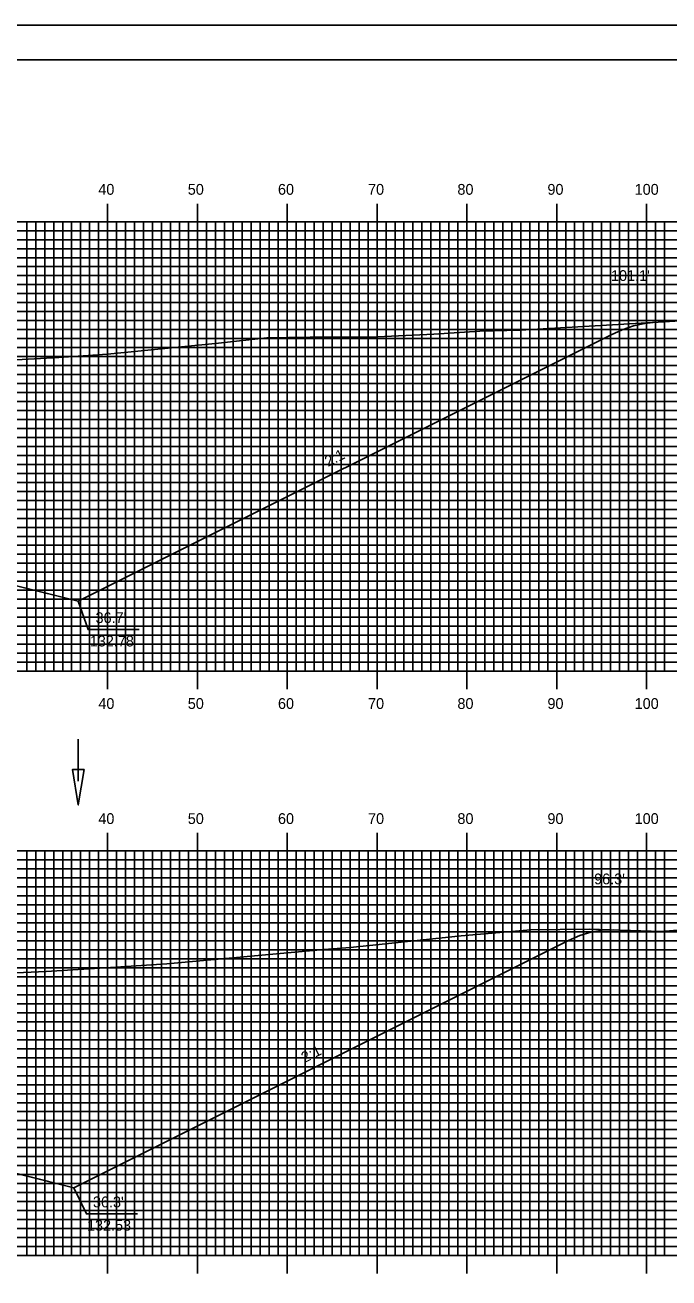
# Model space of a CAD drawing. Extents: x 1783041 to 1783384, y 442591 to 442811.
# Drawn here: x 1783237.3 to 1783309, y 442671.2 to 442810.5 of the extents above; entities that cross this region are included whole.
import ezdxf

# ---------------------------------------------------------------- set-up
doc = ezdxf.new("R2010")
doc.units = 0
for name, color, linetype in [('ANNOTATION', 7, 'Continuous'), ('BORDER', 7, 'Continuous'), ('D_Drainage_Ditch_Line', 7, 'Continuous'), ('D_Roadway_Centerline', 7, 'Continuous'), ('D_Roadway_SlopeLines', 7, 'Continuous'), ('D_Text_Standard', 7, 'Continuous'), ('H_V ANNOTATION', 7, 'Continuous'), ('MAJOR', 7, 'Continuous'), ('MINOR', 7, 'Continuous'), ('PLOT BOUNDARY', 7, 'Continuous'), ('S_Roadway_Centerline', 7, 'Continuous')]:
    doc.layers.add(name, color=color, linetype=linetype)

msp = doc.modelspace()

# ---------------------------------------------------------------- linework, layer by layer
at = {"layer": 'ANNOTATION'}
for points in [[(1783249.98, 442743.3), (1783244.29, 442743.3), (1783243.2, 442746.45)], [(1783249.8, 442678.3), (1783244.11, 442678.3), (1783242.72, 442681.2)]]:
    msp.add_lwpolyline(points, dxfattribs=at)
at = {"layer": 'BORDER'}
msp.add_lwpolyline([(1783056.86, 442596.67), (1783376.86, 442596.67), (1783376.86, 442806.67), (1783056.86, 442806.67)], close=True, dxfattribs=at)
at = {"layer": 'D_Drainage_Ditch_Line'}
msp.add_line((1783243.2, 442726.42), (1783243.2, 442731.12), dxfattribs=at)
msp.add_lwpolyline([(1783243.86, 442727.73), (1783242.54, 442727.73), (1783243.2, 442723.8)], close=True, dxfattribs=at)
at = {"layer": 'D_Roadway_Centerline'}
for points in [[(1783130.65, 442766.39), (1783131.9, 442766.43), (1783133.15, 442766.28), (1783134.4, 442765.93), (1783135.65, 442765.4), (1783172.29, 442747.09), (1783176.29, 442748.09), (1783186.46, 442750.63), (1783194.46, 442750.95), (1783206.46, 442751.19), (1783218.46, 442750.95), (1783226.46, 442750.63), (1783236.63, 442748.09), (1783243.2, 442746.45), (1783302.51, 442776.1), (1783303.76, 442776.66), (1783305.01, 442777.08), (1783306.26, 442777.35), (1783307.51, 442777.49)], [(1783136.28, 442698.26), (1783137.53, 442698.27), (1783138.78, 442698.11), (1783140.03, 442697.76), (1783141.28, 442697.22), (1783172.29, 442681.72), (1783176.29, 442682.72), (1783186.46, 442685.26), (1783194.46, 442685.58), (1783206.46, 442685.82), (1783218.46, 442685.58), (1783226.46, 442685.26), (1783236.63, 442682.72), (1783242.72, 442681.2), (1783297.77, 442708.72), (1783299.02, 442709.26), (1783300.27, 442709.64), (1783301.52, 442709.85), (1783302.77, 442709.89)]]:
    msp.add_lwpolyline(points, dxfattribs=at)
at = {"layer": 'D_Roadway_SlopeLines'}
for points in [[(1783243.2, 442746.45), (1783302.51, 442776.1), (1783303.76, 442776.66), (1783305.01, 442777.08), (1783306.26, 442777.35), (1783307.51, 442777.49)], [(1783226.46, 442750.63), (1783243.2, 442746.45)], [(1783242.72, 442681.2), (1783297.77, 442708.72), (1783299.02, 442709.26), (1783300.27, 442709.64), (1783301.52, 442709.85), (1783302.77, 442709.89)], [(1783226.46, 442685.26), (1783242.72, 442681.2)]]:
    msp.add_lwpolyline(points, dxfattribs=at)
at = {"layer": 'MAJOR'}
for p, q in [((1783246.46, 442790.67), (1783246.46, 442788.67)), ((1783256.46, 442790.67), (1783256.46, 442788.67)), ((1783266.46, 442790.67), (1783266.46, 442788.67)), ((1783276.46, 442790.67), (1783276.46, 442788.67)), ((1783286.46, 442790.67), (1783286.46, 442788.67)), ((1783296.46, 442790.67), (1783296.46, 442788.67)), ((1783306.46, 442790.67), (1783306.46, 442788.67)), ((1783066.46, 442788.67), (1783346.46, 442788.67)), ((1783066.46, 442788.67), (1783346.46, 442788.67)), ((1783246.46, 442738.67), (1783246.46, 442788.67)), ((1783256.46, 442738.67), (1783256.46, 442788.67)), ((1783266.46, 442738.67), (1783266.46, 442788.67)), ((1783276.46, 442738.67), (1783276.46, 442788.67)), ((1783286.46, 442738.67), (1783286.46, 442788.67)), ((1783296.46, 442738.67), (1783296.46, 442788.67)), ((1783306.46, 442738.67), (1783306.46, 442788.67)), ((1783066.46, 442783.67), (1783346.46, 442783.67)), ((1783066.46, 442778.67), (1783346.46, 442778.67)), ((1783066.46, 442773.67), (1783346.46, 442773.67)), ((1783066.46, 442768.67), (1783346.46, 442768.67)), ((1783066.46, 442763.67), (1783346.46, 442763.67)), ((1783066.46, 442758.67), (1783346.46, 442758.67)), ((1783066.46, 442753.67), (1783346.46, 442753.67)), ((1783066.46, 442748.67), (1783346.46, 442748.67)), ((1783066.46, 442743.67), (1783346.46, 442743.67)), ((1783066.46, 442738.67), (1783346.46, 442738.67)), ((1783066.46, 442738.67), (1783346.46, 442738.67)), ((1783246.46, 442736.66), (1783246.46, 442738.67)), ((1783256.46, 442736.66), (1783256.46, 442738.67)), ((1783266.46, 442736.66), (1783266.46, 442738.67)), ((1783276.46, 442736.66), (1783276.46, 442738.67)), ((1783286.46, 442736.66), (1783286.46, 442738.67)), ((1783296.46, 442736.66), (1783296.46, 442738.67)), ((1783306.46, 442736.66), (1783306.46, 442738.67)), ((1783246.46, 442720.67), (1783246.46, 442718.67)), ((1783256.46, 442720.67), (1783256.46, 442718.67)), ((1783266.46, 442720.67), (1783266.46, 442718.67)), ((1783276.46, 442720.67), (1783276.46, 442718.67)), ((1783286.46, 442720.67), (1783286.46, 442718.67)), ((1783296.46, 442720.67), (1783296.46, 442718.67)), ((1783306.46, 442720.67), (1783306.46, 442718.67)), ((1783066.46, 442718.67), (1783346.46, 442718.67)), ((1783066.46, 442718.67), (1783346.46, 442718.67)), ((1783246.46, 442673.67), (1783246.46, 442718.67)), ((1783256.46, 442673.67), (1783256.46, 442718.67)), ((1783266.46, 442673.67), (1783266.46, 442718.67)), ((1783276.46, 442673.67), (1783276.46, 442718.67)), ((1783286.46, 442673.67), (1783286.46, 442718.67)), ((1783296.46, 442673.67), (1783296.46, 442718.67)), ((1783306.46, 442673.67), (1783306.46, 442718.67)), ((1783066.46, 442713.67), (1783346.46, 442713.67)), ((1783066.46, 442708.67), (1783346.46, 442708.67)), ((1783066.46, 442703.67), (1783346.46, 442703.67)), ((1783066.46, 442698.67), (1783346.46, 442698.67)), ((1783066.46, 442693.67), (1783346.46, 442693.67)), ((1783066.46, 442688.67), (1783346.46, 442688.67)), ((1783066.46, 442683.67), (1783346.46, 442683.67)), ((1783066.46, 442678.67), (1783346.46, 442678.67)), ((1783066.46, 442673.67), (1783346.46, 442673.67)), ((1783066.46, 442673.67), (1783346.46, 442673.67)), ((1783246.46, 442671.66), (1783246.46, 442673.67)), ((1783256.46, 442671.66), (1783256.46, 442673.67)), ((1783266.46, 442671.66), (1783266.46, 442673.67)), ((1783276.46, 442671.66), (1783276.46, 442673.67)), ((1783286.46, 442671.66), (1783286.46, 442673.67)), ((1783296.46, 442671.66), (1783296.46, 442673.67)), ((1783306.46, 442671.66), (1783306.46, 442673.67))]:
    msp.add_line(p, q, dxfattribs=at)
at = {"layer": 'MINOR'}
for p, q in [((1783237.46, 442738.67), (1783237.46, 442788.67)), ((1783238.46, 442738.67), (1783238.46, 442788.67)), ((1783239.46, 442738.67), (1783239.46, 442788.67)), ((1783240.46, 442738.67), (1783240.46, 442788.67)), ((1783241.46, 442738.67), (1783241.46, 442788.67)), ((1783242.46, 442738.67), (1783242.46, 442788.67)), ((1783243.46, 442738.67), (1783243.46, 442788.67)), ((1783244.46, 442738.67), (1783244.46, 442788.67)), ((1783245.46, 442738.67), (1783245.46, 442788.67)), ((1783247.46, 442738.67), (1783247.46, 442788.67)), ((1783248.46, 442738.67), (1783248.46, 442788.67)), ((1783249.46, 442738.67), (1783249.46, 442788.67)), ((1783250.46, 442738.67), (1783250.46, 442788.67)), ((1783251.46, 442738.67), (1783251.46, 442788.67)), ((1783252.46, 442738.67), (1783252.46, 442788.67)), ((1783253.46, 442738.67), (1783253.46, 442788.67)), ((1783254.46, 442738.67), (1783254.46, 442788.67)), ((1783255.46, 442738.67), (1783255.46, 442788.67)), ((1783257.46, 442738.67), (1783257.46, 442788.67)), ((1783258.46, 442738.67), (1783258.46, 442788.67)), ((1783259.46, 442738.67), (1783259.46, 442788.67)), ((1783260.46, 442738.67), (1783260.46, 442788.67)), ((1783261.46, 442738.67), (1783261.46, 442788.67)), ((1783262.46, 442738.67), (1783262.46, 442788.67)), ((1783263.46, 442738.67), (1783263.46, 442788.67)), ((1783264.46, 442738.67), (1783264.46, 442788.67)), ((1783265.46, 442738.67), (1783265.46, 442788.67)), ((1783267.46, 442738.67), (1783267.46, 442788.67)), ((1783268.46, 442738.67), (1783268.46, 442788.67)), ((1783269.46, 442738.67), (1783269.46, 442788.67)), ((1783270.46, 442738.67), (1783270.46, 442788.67)), ((1783271.46, 442738.67), (1783271.46, 442788.67)), ((1783272.46, 442738.67), (1783272.46, 442788.67)), ((1783273.46, 442738.67), (1783273.46, 442788.67)), ((1783274.46, 442738.67), (1783274.46, 442788.67)), ((1783275.46, 442738.67), (1783275.46, 442788.67)), ((1783277.46, 442738.67), (1783277.46, 442788.67)), ((1783278.46, 442738.67), (1783278.46, 442788.67)), ((1783279.46, 442738.67), (1783279.46, 442788.67)), ((1783280.46, 442738.67), (1783280.46, 442788.67)), ((1783281.46, 442738.67), (1783281.46, 442788.67)), ((1783282.46, 442738.67), (1783282.46, 442788.67)), ((1783283.46, 442738.67), (1783283.46, 442788.67)), ((1783284.46, 442738.67), (1783284.46, 442788.67)), ((1783285.46, 442738.67), (1783285.46, 442788.67)), ((1783287.46, 442738.67), (1783287.46, 442788.67)), ((1783288.46, 442738.67), (1783288.46, 442788.67)), ((1783289.46, 442738.67), (1783289.46, 442788.67)), ((1783290.46, 442738.67), (1783290.46, 442788.67)), ((1783291.46, 442738.67), (1783291.46, 442788.67)), ((1783292.46, 442738.67), (1783292.46, 442788.67)), ((1783293.46, 442738.67), (1783293.46, 442788.67)), ((1783294.46, 442738.67), (1783294.46, 442788.67)), ((1783295.46, 442738.67), (1783295.46, 442788.67)), ((1783297.46, 442738.67), (1783297.46, 442788.67)), ((1783298.46, 442738.67), (1783298.46, 442788.67)), ((1783299.46, 442738.67), (1783299.46, 442788.67)), ((1783300.46, 442738.67), (1783300.46, 442788.67)), ((1783301.46, 442738.67), (1783301.46, 442788.67)), ((1783302.46, 442738.67), (1783302.46, 442788.67)), ((1783303.46, 442738.67), (1783303.46, 442788.67)), ((1783304.46, 442738.67), (1783304.46, 442788.67)), ((1783305.46, 442738.67), (1783305.46, 442788.67)), ((1783307.46, 442738.67), (1783307.46, 442788.67)), ((1783308.46, 442738.67), (1783308.46, 442788.67)), ((1783066.46, 442787.67), (1783346.46, 442787.67)), ((1783066.46, 442786.67), (1783346.46, 442786.67)), ((1783066.46, 442785.67), (1783346.46, 442785.67)), ((1783066.46, 442784.67), (1783346.46, 442784.67)), ((1783066.46, 442782.67), (1783346.46, 442782.67)), ((1783066.46, 442781.67), (1783346.46, 442781.67)), ((1783066.46, 442780.67), (1783346.46, 442780.67)), ((1783066.46, 442779.67), (1783346.46, 442779.67)), ((1783066.46, 442777.67), (1783346.46, 442777.67)), ((1783066.46, 442776.67), (1783346.46, 442776.67)), ((1783066.46, 442775.67), (1783346.46, 442775.67)), ((1783066.46, 442774.67), (1783346.46, 442774.67)), ((1783066.46, 442772.67), (1783346.46, 442772.67)), ((1783066.46, 442771.67), (1783346.46, 442771.67)), ((1783066.46, 442770.67), (1783346.46, 442770.67)), ((1783066.46, 442769.67), (1783346.46, 442769.67)), ((1783066.46, 442767.67), (1783346.46, 442767.67)), ((1783066.46, 442766.67), (1783346.46, 442766.67)), ((1783066.46, 442765.67), (1783346.46, 442765.67)), ((1783066.46, 442764.67), (1783346.46, 442764.67)), ((1783066.46, 442762.67), (1783346.46, 442762.67)), ((1783066.46, 442761.67), (1783346.46, 442761.67)), ((1783066.46, 442760.67), (1783346.46, 442760.67)), ((1783066.46, 442759.67), (1783346.46, 442759.67)), ((1783066.46, 442757.67), (1783346.46, 442757.67)), ((1783066.46, 442756.67), (1783346.46, 442756.67)), ((1783066.46, 442755.67), (1783346.46, 442755.67)), ((1783066.46, 442754.67), (1783346.46, 442754.67)), ((1783066.46, 442752.67), (1783346.46, 442752.67)), ((1783066.46, 442751.67), (1783346.46, 442751.67)), ((1783066.46, 442750.67), (1783346.46, 442750.67)), ((1783066.46, 442749.67), (1783346.46, 442749.67)), ((1783066.46, 442747.67), (1783346.46, 442747.67)), ((1783066.46, 442746.67), (1783346.46, 442746.67)), ((1783066.46, 442745.67), (1783346.46, 442745.67)), ((1783066.46, 442744.67), (1783346.46, 442744.67)), ((1783066.46, 442742.67), (1783346.46, 442742.67)), ((1783066.46, 442741.67), (1783346.46, 442741.67)), ((1783066.46, 442740.67), (1783346.46, 442740.67)), ((1783066.46, 442739.67), (1783346.46, 442739.67)), ((1783237.46, 442673.67), (1783237.46, 442718.67)), ((1783238.46, 442673.67), (1783238.46, 442718.67)), ((1783239.46, 442673.67), (1783239.46, 442718.67)), ((1783240.46, 442673.67), (1783240.46, 442718.67)), ((1783241.46, 442673.67), (1783241.46, 442718.67)), ((1783242.46, 442673.67), (1783242.46, 442718.67)), ((1783243.46, 442673.67), (1783243.46, 442718.67)), ((1783244.46, 442673.67), (1783244.46, 442718.67)), ((1783245.46, 442673.67), (1783245.46, 442718.67)), ((1783247.46, 442673.67), (1783247.46, 442718.67)), ((1783248.46, 442673.67), (1783248.46, 442718.67)), ((1783249.46, 442673.67), (1783249.46, 442718.67)), ((1783250.46, 442673.67), (1783250.46, 442718.67)), ((1783251.46, 442673.67), (1783251.46, 442718.67)), ((1783252.46, 442673.67), (1783252.46, 442718.67)), ((1783253.46, 442673.67), (1783253.46, 442718.67)), ((1783254.46, 442673.67), (1783254.46, 442718.67)), ((1783255.46, 442673.67), (1783255.46, 442718.67)), ((1783257.46, 442673.67), (1783257.46, 442718.67)), ((1783258.46, 442673.67), (1783258.46, 442718.67)), ((1783259.46, 442673.67), (1783259.46, 442718.67)), ((1783260.46, 442673.67), (1783260.46, 442718.67)), ((1783261.46, 442673.67), (1783261.46, 442718.67)), ((1783262.46, 442673.67), (1783262.46, 442718.67)), ((1783263.46, 442673.67), (1783263.46, 442718.67)), ((1783264.46, 442673.67), (1783264.46, 442718.67)), ((1783265.46, 442673.67), (1783265.46, 442718.67)), ((1783267.46, 442673.67), (1783267.46, 442718.67)), ((1783268.46, 442673.67), (1783268.46, 442718.67)), ((1783269.46, 442673.67), (1783269.46, 442718.67)), ((1783270.46, 442673.67), (1783270.46, 442718.67)), ((1783271.46, 442673.67), (1783271.46, 442718.67)), ((1783272.46, 442673.67), (1783272.46, 442718.67)), ((1783273.46, 442673.67), (1783273.46, 442718.67)), ((1783274.46, 442673.67), (1783274.46, 442718.67)), ((1783275.46, 442673.67), (1783275.46, 442718.67)), ((1783277.46, 442673.67), (1783277.46, 442718.67)), ((1783278.46, 442673.67), (1783278.46, 442718.67)), ((1783279.46, 442673.67), (1783279.46, 442718.67)), ((1783280.46, 442673.67), (1783280.46, 442718.67)), ((1783281.46, 442673.67), (1783281.46, 442718.67)), ((1783282.46, 442673.67), (1783282.46, 442718.67)), ((1783283.46, 442673.67), (1783283.46, 442718.67)), ((1783284.46, 442673.67), (1783284.46, 442718.67)), ((1783285.46, 442673.67), (1783285.46, 442718.67)), ((1783287.46, 442673.67), (1783287.46, 442718.67)), ((1783288.46, 442673.67), (1783288.46, 442718.67)), ((1783289.46, 442673.67), (1783289.46, 442718.67)), ((1783290.46, 442673.67), (1783290.46, 442718.67)), ((1783291.46, 442673.67), (1783291.46, 442718.67)), ((1783292.46, 442673.67), (1783292.46, 442718.67)), ((1783293.46, 442673.67), (1783293.46, 442718.67)), ((1783294.46, 442673.67), (1783294.46, 442718.67)), ((1783295.46, 442673.67), (1783295.46, 442718.67)), ((1783297.46, 442673.67), (1783297.46, 442718.67)), ((1783298.46, 442673.67), (1783298.46, 442718.67)), ((1783299.46, 442673.67), (1783299.46, 442718.67)), ((1783300.46, 442673.67), (1783300.46, 442718.67)), ((1783301.46, 442673.67), (1783301.46, 442718.67)), ((1783302.46, 442673.67), (1783302.46, 442718.67)), ((1783303.46, 442673.67), (1783303.46, 442718.67)), ((1783304.46, 442673.67), (1783304.46, 442718.67)), ((1783305.46, 442673.67), (1783305.46, 442718.67)), ((1783307.46, 442673.67), (1783307.46, 442718.67)), ((1783308.46, 442673.67), (1783308.46, 442718.67)), ((1783066.46, 442717.67), (1783346.46, 442717.67)), ((1783066.46, 442716.67), (1783346.46, 442716.67)), ((1783066.46, 442715.67), (1783346.46, 442715.67)), ((1783066.46, 442714.67), (1783346.46, 442714.67)), ((1783066.46, 442712.67), (1783346.46, 442712.67)), ((1783066.46, 442711.67), (1783346.46, 442711.67)), ((1783066.46, 442710.67), (1783346.46, 442710.67)), ((1783066.46, 442709.67), (1783346.46, 442709.67)), ((1783066.46, 442707.67), (1783346.46, 442707.67)), ((1783066.46, 442706.67), (1783346.46, 442706.67)), ((1783066.46, 442705.67), (1783346.46, 442705.67)), ((1783066.46, 442704.67), (1783346.46, 442704.67)), ((1783066.46, 442702.67), (1783346.46, 442702.67)), ((1783066.46, 442701.67), (1783346.46, 442701.67)), ((1783066.46, 442700.67), (1783346.46, 442700.67)), ((1783066.46, 442699.67), (1783346.46, 442699.67)), ((1783066.46, 442697.67), (1783346.46, 442697.67)), ((1783066.46, 442696.67), (1783346.46, 442696.67)), ((1783066.46, 442695.67), (1783346.46, 442695.67)), ((1783066.46, 442694.67), (1783346.46, 442694.67)), ((1783066.46, 442692.67), (1783346.46, 442692.67)), ((1783066.46, 442691.67), (1783346.46, 442691.67)), ((1783066.46, 442690.67), (1783346.46, 442690.67)), ((1783066.46, 442689.67), (1783346.46, 442689.67)), ((1783066.46, 442687.67), (1783346.46, 442687.67)), ((1783066.46, 442686.67), (1783346.46, 442686.67)), ((1783066.46, 442685.67), (1783346.46, 442685.67)), ((1783066.46, 442684.67), (1783346.46, 442684.67)), ((1783066.46, 442682.67), (1783346.46, 442682.67)), ((1783066.46, 442681.67), (1783346.46, 442681.67)), ((1783066.46, 442680.67), (1783346.46, 442680.67)), ((1783066.46, 442679.67), (1783346.46, 442679.67)), ((1783066.46, 442677.67), (1783346.46, 442677.67)), ((1783066.46, 442676.67), (1783346.46, 442676.67)), ((1783066.46, 442675.67), (1783346.46, 442675.67)), ((1783066.46, 442674.67), (1783346.46, 442674.67))]:
    msp.add_line(p, q, dxfattribs=at)
at = {"layer": 'PLOT BOUNDARY'}
msp.add_lwpolyline([(1783040.67, 442590.55), (1783380.67, 442590.55), (1783380.67, 442810.55), (1783040.67, 442810.55)], close=True, dxfattribs=at)
at = {"layer": 'S_Roadway_Centerline'}
for points in [[(1783234.92, 442773.24), (1783241.03, 442773.57), (1783246.45, 442773.95), (1783258.82, 442775.16), (1783264.19, 442775.75), (1783269.01, 442775.81), (1783275.73, 442775.84), (1783282.77, 442776.15), (1783287.9, 442776.49), (1783292.39, 442776.6), (1783305.86, 442777.4), (1783313.39, 442777.82), (1783320.97, 442778.34), (1783329.14, 442778.77), (1783333, 442778.98), (1783336.56, 442779.24), (1783346.46, 442779.75)], [(1783230.35, 442704.87), (1783239.64, 442705.26), (1783247.37, 442705.76), (1783253.07, 442706.1), (1783270.57, 442707.7), (1783273.48, 442707.94), (1783276.7, 442708.27), (1783285.84, 442709.24), (1783293.59, 442709.9), (1783300.08, 442709.98), (1783308.14, 442709.72), (1783316.96, 442710.45), (1783320.97, 442710.8), (1783325.2, 442710.89), (1783332.73, 442711.24), (1783339.69, 442711.38), (1783346.46, 442711.78)]]:
    msp.add_lwpolyline(points, dxfattribs=at)

# ---------------------------------------------------------------- texts
at = {"layer": 'ANNOTATION'}
for p in [(1783271, 442761.38), (1783268.39, 442695.07)]:
    msp.add_text('2:1', height=1.2, rotation=26.5651, dxfattribs=at).set_placement(p)
for s, p in [("36.7'", (1783245.12, 442744.02)), ('132.78', (1783244.48, 442741.42)), ("36.3'", (1783244.83, 442679.03)), ('132.53', (1783244.17, 442676.43))]:
    msp.add_text(s, height=1.2, dxfattribs=at).set_placement(p)
at = {"layer": 'D_Text_Standard'}
for s, p in [("101.1'", (1783302.51, 442782.08)), ("96.3'", (1783300.63, 442714.96))]:
    msp.add_text(s, height=1.2, dxfattribs=at).set_placement(p)
at = {"layer": 'H_V ANNOTATION'}
for s, p in [('40', (1783245.43, 442791.67)), ('50', (1783255.39, 442791.67)), ('60', (1783265.43, 442791.67)), ('70', (1783275.46, 442791.67)), ('80', (1783285.41, 442791.67)), ('90', (1783295.43, 442791.67)), ('100', (1783305.14, 442791.67)), ('40', (1783245.43, 442734.47)), ('50', (1783255.39, 442734.47)), ('60', (1783265.43, 442734.47)), ('70', (1783275.46, 442734.47)), ('80', (1783285.41, 442734.47)), ('90', (1783295.43, 442734.47)), ('100', (1783305.14, 442734.47)), ('40', (1783245.43, 442721.67)), ('50', (1783255.39, 442721.67)), ('60', (1783265.43, 442721.67)), ('70', (1783275.46, 442721.67)), ('80', (1783285.41, 442721.67)), ('90', (1783295.43, 442721.67)), ('100', (1783305.14, 442721.67))]:
    msp.add_text(s, height=1.2, dxfattribs=at).set_placement(p)

doc.saveas('drawing.dxf')
